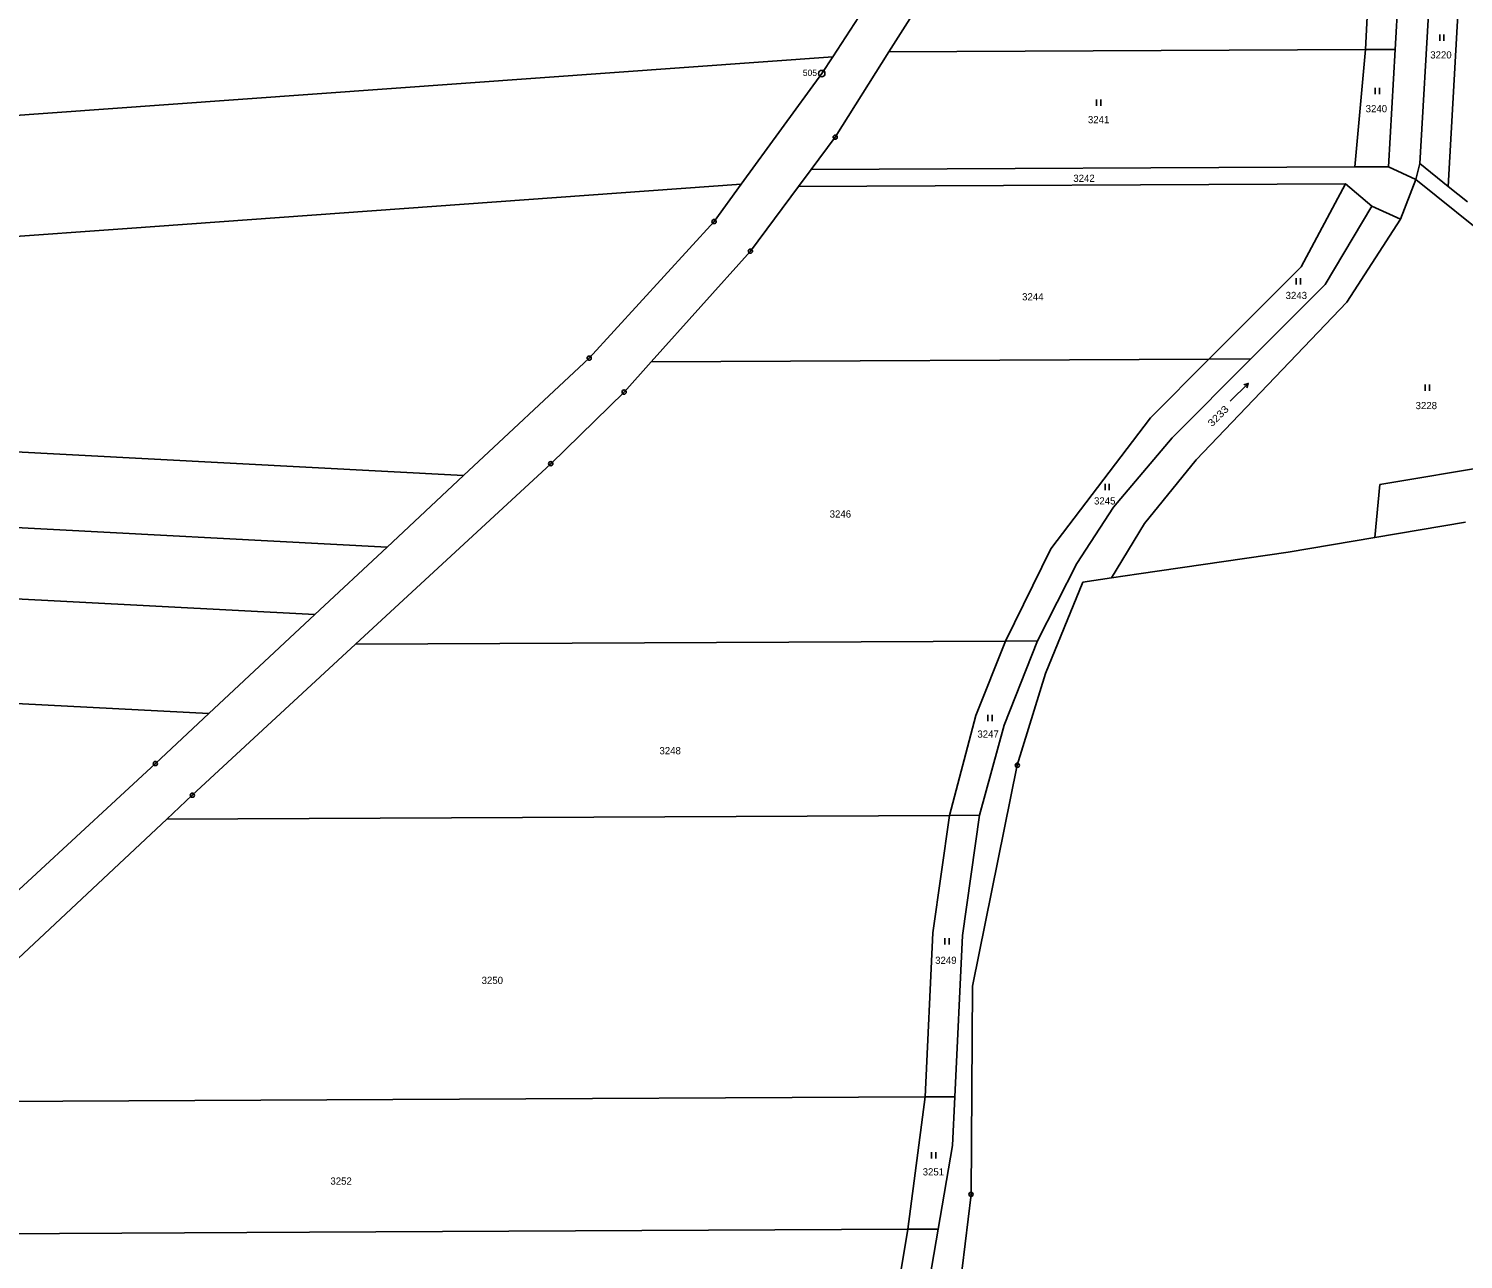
# Model space of a CAD drawing. Extents: x -618848 to -615803, y -1044450 to -1042254.
# Drawn here: x -617212.5 to -616873.5, y -1043993.9 to -1043703.1 of the extents above; entities that cross this region are included whole.
import ezdxf

# ---------------------------------------------------------------- set-up
doc = ezdxf.new("R2010")
doc.units = 0
doc.header["$LTSCALE"] = 0.68
for name, color, linetype, lineweight in [('1', 7, 'Continuous', 25), ('3', 7, 'Continuous', 25), ('8', 7, 'Continuous', 25)]:
    doc.layers.add(name, color=color, linetype=linetype, lineweight=lineweight)
doc.layers.add('2', color=7, linetype='Continuous')

msp = doc.modelspace()

# ---------------------------------------------------------------- linework, layer by layer
at = {"layer": '1'}
for p, q in [((-616891.67, -1043619.84), (-616896.61, -1043708)), ((-616889.57, -1043707.97), (-616884.54, -1043619.77)), ((-617002.72, -1043679.23), (-617022.48, -1043709.69)), ((-616873.94, -1043684.93), (-616877.02, -1043740.36)), ((-617009.18, -1043708.56), (-616995.75, -1043687.3)), ((-616883.73, -1043734.95), (-616881.01, -1043687.13)), ((-617021.89, -1043728.7), (-617009.18, -1043708.56)), ((-616896.61, -1043708), (-617009.18, -1043708.56)), ((-616896.61, -1043708), (-616899.12, -1043735.73)), ((-616896.61, -1043708), (-616889.57, -1043707.97)), ((-616891.15, -1043735.69), (-616889.57, -1043707.97)), ((-617022.48, -1043709.69), (-617179.43, -1043720.98)), ((-617025.07, -1043713.67), (-617022.48, -1043709.69)), ((-617044.1, -1043739.83), (-617025.07, -1043713.67)), ((-617179.43, -1043720.98), (-617336.38, -1043732.26)), ((-617027.58, -1043736.35), (-617021.89, -1043728.7)), ((-616899.12, -1043735.73), (-617027.58, -1043736.35)), ((-616891.15, -1043735.69), (-616899.12, -1043735.73)), ((-616884.69, -1043738.67), (-616891.15, -1043735.69)), ((-616884.69, -1043738.67), (-616883.73, -1043734.95)), ((-616877.02, -1043740.36), (-616883.73, -1043734.95)), ((-617030.57, -1043740.37), (-617027.58, -1043736.35)), ((-616888.31, -1043748.07), (-616884.69, -1043738.67)), ((-616884.69, -1043738.67), (-616857.04, -1043760.94)), ((-617189.22, -1043750.28), (-617044.1, -1043739.83)), ((-617044.1, -1043739.83), (-617050.51, -1043748.64)), ((-617041.93, -1043755.64), (-617030.57, -1043740.37)), ((-617030.57, -1043740.37), (-616901.27, -1043739.74)), ((-616901.27, -1043739.74), (-616911.77, -1043759.31)), ((-616901.27, -1043739.74), (-616895.08, -1043744.98)), ((-616872.49, -1043744.01), (-616877.02, -1043740.36)), ((-616906.09, -1043763.53), (-616895.08, -1043744.98)), ((-616895.08, -1043744.98), (-616888.31, -1043748.07)), ((-617050.51, -1043748.64), (-617080.03, -1043780.92)), ((-616888.31, -1043748.07), (-616900.97, -1043767.7)), ((-617334.35, -1043760.72), (-617189.22, -1043750.28)), ((-617065.38, -1043781.81), (-617041.93, -1043755.64)), ((-616911.77, -1043759.31), (-616933.6, -1043781.17)), ((-616923.66, -1043781.12), (-616906.09, -1043763.53)), ((-616900.97, -1043767.7), (-616936.59, -1043804.98)), ((-617080.03, -1043780.92), (-617109.73, -1043808.68)), ((-617071.77, -1043788.94), (-617065.38, -1043781.81)), ((-617065.38, -1043781.81), (-616933.6, -1043781.17)), ((-616933.6, -1043781.17), (-616947.42, -1043795)), ((-616942.25, -1043799.73), (-616923.66, -1043781.12)), ((-616933.6, -1043781.17), (-616923.66, -1043781.12)), ((-617089.12, -1043805.86), (-617071.77, -1043788.94)), ((-616947.42, -1043795), (-616970.9, -1043825.98)), ((-616956.13, -1043816.14), (-616942.25, -1043799.73)), ((-616821.14, -1043798.62), (-616893.15, -1043810.82)), ((-617109.73, -1043808.68), (-617265.92, -1043800.44)), ((-617135.25, -1043848.53), (-617089.12, -1043805.86)), ((-616936.59, -1043804.98), (-616948.77, -1043819.96)), ((-617127.81, -1043825.57), (-617109.73, -1043808.68)), ((-616893.15, -1043810.82), (-616894.33, -1043823.31)), ((-617308.37, -1043816.04), (-617127.81, -1043825.57)), ((-616964.83, -1043829.49), (-616956.13, -1043816.14)), ((-616948.77, -1043819.96), (-616956.63, -1043832.86)), ((-616894.33, -1043823.31), (-616872.98, -1043819.7)), ((-616914.85, -1043826.79), (-616894.33, -1043823.31)), ((-617127.81, -1043825.57), (-617144.87, -1043841.51)), ((-616970.9, -1043825.98), (-616981.66, -1043847.78)), ((-616950.11, -1043831.91), (-616914.85, -1043826.79)), ((-616974.12, -1043847.74), (-616964.83, -1043829.49)), ((-617144.87, -1043841.51), (-617322.96, -1043832.11)), ((-616972.23, -1043855.46), (-616963.38, -1043833.84)), ((-616963.38, -1043833.84), (-616956.63, -1043832.86)), ((-616956.63, -1043832.86), (-616950.11, -1043831.91)), ((-617169.91, -1043864.91), (-617144.87, -1043841.51)), ((-616981.66, -1043847.78), (-617135.25, -1043848.53)), ((-616988.62, -1043865.41), (-616981.66, -1043847.78)), ((-616974.12, -1043847.74), (-616981.97, -1043867.63)), ((-616981.66, -1043847.78), (-616974.12, -1043847.74)), ((-617173.82, -1043884.21), (-617135.25, -1043848.53)), ((-617344.93, -1043855.67), (-617169.91, -1043864.91)), ((-616978.86, -1043877.12), (-616972.23, -1043855.46)), ((-617169.91, -1043864.91), (-617182.55, -1043876.72)), ((-616994.89, -1043888.97), (-616988.62, -1043865.41)), ((-616981.97, -1043867.63), (-616987.82, -1043888.94)), ((-617182.55, -1043876.72), (-617226.04, -1043916.9)), ((-616989.41, -1043929.35), (-616978.86, -1043877.12)), ((-617179.87, -1043889.87), (-617173.82, -1043884.21)), ((-617232.78, -1043939.4), (-617179.87, -1043889.87)), ((-616994.89, -1043888.97), (-617179.87, -1043889.87)), ((-616994.89, -1043888.97), (-616998.8, -1043916.74)), ((-616987.82, -1043888.94), (-616994.89, -1043888.97)), ((-616991.82, -1043917.4), (-616987.82, -1043888.94)), ((-616998.8, -1043916.74), (-617000.65, -1043955.52)), ((-616993.65, -1043955.49), (-616991.82, -1043917.4)), ((-616989.8, -1043978.54), (-616989.41, -1043929.35)), ((-617126.46, -1043956.14), (-617252.27, -1043956.76)), ((-617000.65, -1043955.52), (-616993.65, -1043955.49)), ((-616993.65, -1043955.49), (-616994.2, -1043966.96)), ((-616994.2, -1043966.96), (-616997.58, -1043986.75)), ((-617146.14, -1043987.48), (-617004.69, -1043986.79)), ((-617013.77, -1044039.95), (-617004.69, -1043986.79)), ((-616997.58, -1043986.75), (-617006.66, -1044039.91)), ((-616997.58, -1043986.75), (-617004.69, -1043986.79)), ((-617287.58, -1043988.18), (-617146.14, -1043987.48))]:
    msp.add_line(p, q, dxfattribs=at)
for points in [[(-617004.69, -1043986.79), (-617000.65, -1043955.52), (-617126.46, -1043956.14)], [(-617009.77, -1044092.86), (-616991.88, -1043996.06), (-616989.8, -1043978.54)]]:
    msp.add_lwpolyline(points, dxfattribs=at)
at = {"layer": '3'}
for p, q in [((-616879.041, -1043705.91), (-616879.041, -1043704.41)), ((-616878.04, -1043705.91), (-616878.04, -1043704.41)), ((-616894.291, -1043718.53), (-616894.291, -1043717.03)), ((-616893.29, -1043718.53), (-616893.29, -1043717.03)), ((-616960.131, -1043721.29), (-616960.131, -1043719.79)), ((-616959.13, -1043721.29), (-616959.13, -1043719.79)), ((-616912.931, -1043763.55), (-616912.931, -1043762.05)), ((-616911.93, -1043763.55), (-616911.93, -1043762.05)), ((-616924.291, -1043786.883), (-616924.627, -1043787.928)), ((-616882.461, -1043788.65), (-616882.461, -1043787.15)), ((-616881.46, -1043788.65), (-616881.46, -1043787.15)), ((-616958.121, -1043812.12), (-616958.121, -1043810.62)), ((-616957.12, -1043812.12), (-616957.12, -1043810.62)), ((-616985.831, -1043866.68), (-616985.831, -1043865.18)), ((-616984.83, -1043866.68), (-616984.83, -1043865.18)), ((-616995.951, -1043919.5), (-616995.951, -1043918)), ((-616994.95, -1043919.5), (-616994.95, -1043918)), ((-616999.101, -1043970.07), (-616999.101, -1043968.57)), ((-616998.1, -1043970.07), (-616998.1, -1043968.57))]:
    msp.add_line(p, q, dxfattribs=at)
msp.add_lwpolyline([(-616928.533, -1043791.125), (-616924.291, -1043786.883), (-616925.336, -1043787.219)], dxfattribs=at)
at = {"layer": '8'}
for centre, radius in [((-617025.07, -1043713.6698), 0.75), ((-617025.07, -1043713.6698), 0.03), ((-617021.89, -1043728.6999), 0.5), ((-617021.89, -1043728.6999), 0.0303), ((-617050.51, -1043748.6399), 0.5), ((-617050.51, -1043748.6399), 0.0303), ((-617041.93, -1043755.6399), 0.5), ((-617041.93, -1043755.6399), 0.0303), ((-617080.03, -1043780.9199), 0.5), ((-617080.03, -1043780.9199), 0.0303), ((-617071.77, -1043788.9399), 0.5), ((-617071.77, -1043788.9399), 0.0303), ((-617089.12, -1043805.8599), 0.5), ((-617089.12, -1043805.8599), 0.0303), ((-617182.55, -1043876.7199), 0.5), ((-617182.55, -1043876.7199), 0.0303), ((-616978.86, -1043877.1199), 0.5), ((-616978.86, -1043877.1199), 0.0303), ((-617173.82, -1043884.2099), 0.5), ((-617173.82, -1043884.2099), 0.0303), ((-616989.8, -1043978.5399), 0.5), ((-616989.8, -1043978.5399), 0.0303)]:
    msp.add_circle(centre, radius, dxfattribs=at)

# ---------------------------------------------------------------- texts
at = {"layer": '2'}
for s, p in [('3220', (-616881.27, -1043710.105)), ('3240', (-616896.53, -1043722.815)), ('3241', (-616962.17, -1043725.405)), ('3242', (-616965.62, -1043739.265)), ('3244', (-616977.72, -1043767.275)), ('3243', (-616915.45, -1043766.955)), ('3228', (-616884.73, -1043792.975)), ('3245', (-616960.73, -1043815.505)), ('3246', (-617023.2, -1043818.605)), ('3247', (-616988.29, -1043870.615)), ('3248', (-617063.42, -1043874.535)), ('3249', (-616998.27, -1043924.075)), ('3250', (-617105.45, -1043928.815)), ('3251', (-617001.22, -1043974.065)), ('3252', (-617141.18, -1043976.245))]:
    msp.add_text(s, height=1.7, dxfattribs=at).set_placement(p)
at = {"layer": '2', "width": 1.15}
msp.add_text('3233', height=1.7, rotation=45, dxfattribs=at).set_placement((-616932.849, -1043797.26))
at = {"layer": '8'}
msp.add_text('505', height=1.5, dxfattribs=at).set_placement((-617029.54, -1043714.235))

doc.saveas('drawing.dxf')
